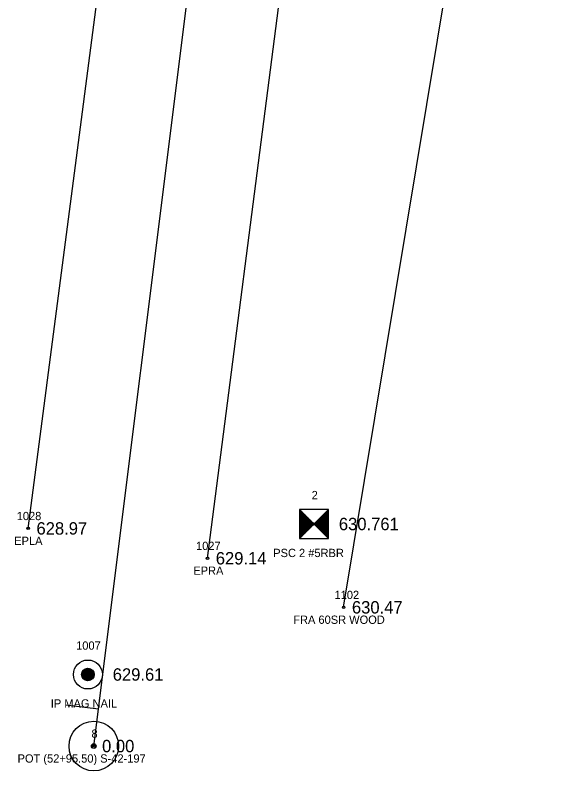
# Model space of a CAD drawing. Extents: x 1694813 to 1696862, y 1086485 to 1091027.
# Drawn here: x 1695856.6 to 1695921.9, y 1087535.6 to 1087627 of the extents above; entities that cross this region are included whole.
import ezdxf

# ---------------------------------------------------------------- set-up
doc = ezdxf.new("R2010")
doc.units = 0
for name, color, linetype in [('RD_EX_DV_Prop_txCode', 7, 'Continuous'), ('RD_EX_DV_PropPin', 7, 'Continuous'), ('RD_EX_Fence_Other', 7, 'Continuous'), ('RD_EX_Fence_Other_txCode', 7, 'Continuous'), ('RD_EX_Road', 7, 'Continuous'), ('RD_EX_Road_txCode', 7, 'Continuous'), ('RD_EX_TX_DV_Prop_ELEV', 7, 'Continuous'), ('RD_EX_TX_Fence_Other_ELEV', 7, 'Continuous'), ('RD_EX_TX_Road_ELEV', 7, 'Continuous'), ('RD_HC_Cl', 7, 'Continuous'), ('RD_HC_Data', 7, 'Continuous'), ('RD_HC_Data_Tic', 7, 'Continuous'), ('RD_HC_Survey', 7, 'Continuous'), ('RD_HC_Survey_ELEV', 7, 'Continuous'), ('RD_HC_txCode', 7, 'Continuous'), ('RD_SMD_Locator', 7, 'Continuous')]:
    doc.layers.add(name, color=color, linetype=linetype)

msp = doc.modelspace()

# ---------------------------------------------------------------- linework, layer by layer
at = {"layer": 'RD_EX_DV_PropPin'}
for p, q in [((1695864.674, 1087547.04), (1695864.674, 1087547.432)), ((1695864.709, 1087546.938), (1695864.709, 1087547.534)), ((1695864.744, 1087546.866), (1695864.744, 1087547.606)), ((1695864.779, 1087546.809), (1695864.779, 1087547.663)), ((1695864.814, 1087546.762), (1695864.814, 1087547.71)), ((1695864.849, 1087546.721), (1695864.849, 1087547.751)), ((1695864.884, 1087546.685), (1695864.884, 1087547.787)), ((1695864.919, 1087546.654), (1695864.919, 1087547.818)), ((1695864.954, 1087546.626), (1695864.954, 1087547.846)), ((1695864.989, 1087546.601), (1695864.989, 1087547.871)), ((1695865.024, 1087546.58), (1695865.024, 1087547.892)), ((1695865.059, 1087546.56), (1695865.059, 1087547.912)), ((1695865.094, 1087546.543), (1695865.094, 1087547.929)), ((1695865.129, 1087546.528), (1695865.129, 1087547.944)), ((1695865.164, 1087546.516), (1695865.164, 1087547.956)), ((1695865.199, 1087546.505), (1695865.199, 1087547.967)), ((1695865.234, 1087546.495), (1695865.234, 1087547.977)), ((1695865.269, 1087546.488), (1695865.269, 1087547.984)), ((1695865.304, 1087546.482), (1695865.304, 1087547.99)), ((1695865.339, 1087546.478), (1695865.339, 1087547.994)), ((1695865.374, 1087546.476), (1695865.374, 1087547.996)), ((1695865.409, 1087546.475), (1695865.409, 1087547.997)), ((1695865.444, 1087546.476), (1695865.444, 1087547.996)), ((1695865.479, 1087546.478), (1695865.479, 1087547.994)), ((1695865.514, 1087546.482), (1695865.514, 1087547.99)), ((1695865.549, 1087546.488), (1695865.549, 1087547.984)), ((1695865.584, 1087546.495), (1695865.584, 1087547.977)), ((1695865.619, 1087546.505), (1695865.619, 1087547.967)), ((1695865.654, 1087546.516), (1695865.654, 1087547.956)), ((1695865.689, 1087546.528), (1695865.689, 1087547.944)), ((1695865.724, 1087546.543), (1695865.724, 1087547.929)), ((1695865.759, 1087546.56), (1695865.759, 1087547.912)), ((1695865.794, 1087546.58), (1695865.794, 1087547.892)), ((1695865.829, 1087546.601), (1695865.829, 1087547.871)), ((1695865.864, 1087546.626), (1695865.864, 1087547.846)), ((1695865.899, 1087546.654), (1695865.899, 1087547.818)), ((1695865.934, 1087546.685), (1695865.934, 1087547.787)), ((1695865.969, 1087546.721), (1695865.969, 1087547.751)), ((1695866.004, 1087546.762), (1695866.004, 1087547.71)), ((1695866.039, 1087546.809), (1695866.039, 1087547.663)), ((1695866.074, 1087546.866), (1695866.074, 1087547.606)), ((1695866.109, 1087546.938), (1695866.109, 1087547.534)), ((1695866.144, 1087547.04), (1695866.144, 1087547.432))]:
    msp.add_line(p, q, dxfattribs=at)
for radius in [1.75, 0.761]:
    msp.add_circle((1695865.409, 1087547.236), radius, dxfattribs=at)
at = {"layer": 'RD_EX_Fence_Other'}
msp.add_lwpolyline([(1695896.342, 1087555.362), (1695913.969, 1087661.925), (1695929.73, 1087763.599), (1695939.841, 1087832.071), (1696009.841, 1087821.325)], dxfattribs=at)
at = {"layer": 'RD_EX_Road'}
for points in [[(1695879.875, 1087561.295), (1695893.332, 1087665.713), (1695905.959, 1087767.16), (1695918.657, 1087869.542), (1695930.865, 1087972.819), (1695936.258, 1088023.677), (1695942.136, 1088076.32), (1695948.067, 1088128.166), (1695955.04, 1088181.397), (1695962.876, 1088230.723), (1695971.68, 1088284.642), (1695982.023, 1088336.119), (1695993.277, 1088388.477), (1696018.751, 1088494.485), (1696045.231, 1088599.952), (1696055.716, 1088654.408), (1696060.146, 1088705.346), (1696055.832, 1088758.02), (1696044.006, 1088812.164), (1696026.404, 1088860.327), (1696000.406, 1088911.477), (1695972.46, 1088953.819), (1695939.476, 1088998.727), (1695931.206, 1088992.882)], [(1695858.187, 1087564.905), (1695871.711, 1087668.821), (1695884.505, 1087774.687), (1695887.48, 1087794.197), (1695897.565, 1087873.427), (1695908.916, 1087975.758), (1695914.491, 1088029.245), (1695917.654, 1088054.804), (1695920.274, 1088079.088), (1695926.979, 1088130.264), (1695934.746, 1088185.086), (1695942.155, 1088234.618), (1695951.36, 1088288.056), (1695961.479, 1088338.405), (1695972.862, 1088394.133), (1695998.526, 1088499.671), (1696024.807, 1088603.859), (1696034.83, 1088656.783)]]:
    msp.add_lwpolyline(points, dxfattribs=at)
at = {"layer": 'RD_HC_Cl'}
msp.add_line((1695866.122, 1087538.577), (1695910.685, 1087894.288), dxfattribs=at)
at = {"layer": 'RD_HC_Data'}
for radius in [3, 0.282]:
    msp.add_circle((1695866.122, 1087538.577), radius, dxfattribs=at)
at = {"layer": 'RD_HC_Data_Tic'}
msp.add_line((1695866.681, 1087543.042), (1695862.712, 1087543.539), dxfattribs=at)
at = {"layer": 'RD_HC_Survey'}
for p, q in [((1695891.011, 1087567.188), (1695894.511, 1087563.688)), ((1695894.511, 1087567.188), (1695891.011, 1087563.688)), ((1695891.035, 1087567.163), (1695891.035, 1087563.713)), ((1695891.06, 1087567.139), (1695891.06, 1087563.738)), ((1695891.085, 1087567.114), (1695891.085, 1087563.762)), ((1695891.11, 1087567.089), (1695891.11, 1087563.787)), ((1695891.134, 1087567.064), (1695891.134, 1087563.812)), ((1695891.159, 1087567.04), (1695891.159, 1087563.837)), ((1695891.184, 1087567.015), (1695891.184, 1087563.861)), ((1695891.209, 1087566.99), (1695891.209, 1087563.886)), ((1695891.233, 1087566.965), (1695891.233, 1087563.911)), ((1695891.258, 1087566.941), (1695891.258, 1087563.936)), ((1695891.283, 1087566.916), (1695891.283, 1087563.96)), ((1695891.308, 1087566.891), (1695891.308, 1087563.985)), ((1695891.332, 1087566.866), (1695891.332, 1087564.01)), ((1695891.357, 1087566.842), (1695891.357, 1087564.035)), ((1695891.382, 1087566.817), (1695891.382, 1087564.059)), ((1695891.407, 1087566.792), (1695891.407, 1087564.084)), ((1695891.431, 1087566.767), (1695891.431, 1087564.109)), ((1695891.456, 1087566.743), (1695891.456, 1087564.134)), ((1695891.481, 1087566.718), (1695891.481, 1087564.158)), ((1695891.506, 1087566.693), (1695891.506, 1087564.183)), ((1695891.53, 1087566.668), (1695891.53, 1087564.208)), ((1695891.555, 1087566.644), (1695891.555, 1087564.233)), ((1695891.58, 1087566.619), (1695891.58, 1087564.257)), ((1695891.605, 1087566.594), (1695891.605, 1087564.282)), ((1695891.629, 1087566.569), (1695891.629, 1087564.307)), ((1695891.654, 1087566.545), (1695891.654, 1087564.332)), ((1695891.679, 1087566.52), (1695891.679, 1087564.356)), ((1695891.704, 1087566.495), (1695891.704, 1087564.381)), ((1695891.728, 1087566.47), (1695891.728, 1087564.406)), ((1695891.753, 1087566.446), (1695891.753, 1087564.431)), ((1695891.778, 1087566.421), (1695891.778, 1087564.455)), ((1695891.803, 1087566.396), (1695891.803, 1087564.48)), ((1695893.719, 1087566.396), (1695893.719, 1087564.48)), ((1695893.743, 1087566.421), (1695893.743, 1087564.455)), ((1695893.768, 1087566.446), (1695893.768, 1087564.431)), ((1695893.793, 1087566.47), (1695893.793, 1087564.406)), ((1695893.818, 1087566.495), (1695893.818, 1087564.381)), ((1695893.842, 1087566.52), (1695893.842, 1087564.356)), ((1695893.867, 1087566.545), (1695893.867, 1087564.332)), ((1695893.892, 1087566.569), (1695893.892, 1087564.307)), ((1695893.917, 1087566.594), (1695893.917, 1087564.282)), ((1695893.941, 1087566.619), (1695893.941, 1087564.257)), ((1695893.966, 1087566.644), (1695893.966, 1087564.233)), ((1695893.991, 1087566.668), (1695893.991, 1087564.208)), ((1695894.016, 1087566.693), (1695894.016, 1087564.183)), ((1695894.04, 1087566.718), (1695894.04, 1087564.158)), ((1695894.065, 1087566.743), (1695894.065, 1087564.134)), ((1695894.09, 1087566.767), (1695894.09, 1087564.109)), ((1695894.115, 1087566.792), (1695894.115, 1087564.084)), ((1695894.139, 1087566.817), (1695894.139, 1087564.059)), ((1695894.164, 1087566.842), (1695894.164, 1087564.035)), ((1695894.189, 1087566.866), (1695894.189, 1087564.01)), ((1695894.214, 1087566.891), (1695894.214, 1087563.985)), ((1695894.238, 1087566.916), (1695894.238, 1087563.96)), ((1695894.263, 1087566.941), (1695894.263, 1087563.936)), ((1695894.288, 1087566.965), (1695894.288, 1087563.911)), ((1695894.313, 1087566.99), (1695894.313, 1087563.886)), ((1695894.337, 1087567.015), (1695894.337, 1087563.861)), ((1695894.362, 1087567.04), (1695894.362, 1087563.837)), ((1695894.387, 1087567.064), (1695894.387, 1087563.812)), ((1695894.412, 1087567.089), (1695894.412, 1087563.787)), ((1695894.436, 1087567.114), (1695894.436, 1087563.762)), ((1695894.461, 1087567.139), (1695894.461, 1087563.738)), ((1695894.486, 1087567.163), (1695894.486, 1087563.713)), ((1695891.827, 1087566.371), (1695891.827, 1087564.505)), ((1695891.852, 1087566.347), (1695891.852, 1087564.53)), ((1695891.877, 1087566.322), (1695891.877, 1087564.554)), ((1695891.902, 1087566.297), (1695891.902, 1087564.579)), ((1695891.926, 1087566.272), (1695891.926, 1087564.604)), ((1695891.951, 1087566.248), (1695891.951, 1087564.629)), ((1695891.976, 1087566.223), (1695891.976, 1087564.653)), ((1695892.001, 1087566.198), (1695892.001, 1087564.678)), ((1695892.025, 1087566.173), (1695892.025, 1087564.703)), ((1695892.05, 1087566.149), (1695892.05, 1087564.728)), ((1695892.075, 1087566.124), (1695892.075, 1087564.752)), ((1695892.1, 1087566.099), (1695892.1, 1087564.777)), ((1695892.124, 1087566.075), (1695892.124, 1087564.802)), ((1695892.149, 1087566.05), (1695892.149, 1087564.827)), ((1695892.174, 1087566.025), (1695892.174, 1087564.851)), ((1695892.199, 1087566), (1695892.199, 1087564.876)), ((1695892.223, 1087565.976), (1695892.223, 1087564.901)), ((1695892.248, 1087565.951), (1695892.248, 1087564.926)), ((1695892.273, 1087565.926), (1695892.273, 1087564.95)), ((1695892.298, 1087565.901), (1695892.298, 1087564.975)), ((1695892.322, 1087565.877), (1695892.322, 1087565)), ((1695892.347, 1087565.852), (1695892.347, 1087565.025)), ((1695892.372, 1087565.827), (1695892.372, 1087565.049)), ((1695892.397, 1087565.802), (1695892.397, 1087565.074)), ((1695892.421, 1087565.778), (1695892.421, 1087565.099)), ((1695892.446, 1087565.753), (1695892.446, 1087565.124)), ((1695892.471, 1087565.728), (1695892.471, 1087565.148)), ((1695892.496, 1087565.703), (1695892.496, 1087565.173)), ((1695892.52, 1087565.679), (1695892.52, 1087565.198)), ((1695892.545, 1087565.654), (1695892.545, 1087565.223)), ((1695892.57, 1087565.629), (1695892.57, 1087565.247)), ((1695892.595, 1087565.604), (1695892.595, 1087565.272)), ((1695892.619, 1087565.58), (1695892.619, 1087565.297)), ((1695892.644, 1087565.555), (1695892.644, 1087565.322)), ((1695892.669, 1087565.53), (1695892.669, 1087565.346)), ((1695892.694, 1087565.505), (1695892.694, 1087565.371)), ((1695892.718, 1087565.481), (1695892.718, 1087565.396)), ((1695892.803, 1087565.481), (1695892.803, 1087565.396)), ((1695892.828, 1087565.505), (1695892.828, 1087565.371)), ((1695892.852, 1087565.53), (1695892.852, 1087565.346)), ((1695892.877, 1087565.555), (1695892.877, 1087565.322)), ((1695892.902, 1087565.58), (1695892.902, 1087565.297)), ((1695892.927, 1087565.604), (1695892.927, 1087565.272)), ((1695892.951, 1087565.629), (1695892.951, 1087565.247)), ((1695892.976, 1087565.654), (1695892.976, 1087565.223)), ((1695893.001, 1087565.679), (1695893.001, 1087565.198)), ((1695893.026, 1087565.703), (1695893.026, 1087565.173)), ((1695893.05, 1087565.728), (1695893.05, 1087565.148)), ((1695893.075, 1087565.753), (1695893.075, 1087565.124)), ((1695893.1, 1087565.778), (1695893.1, 1087565.099)), ((1695893.125, 1087565.802), (1695893.125, 1087565.074)), ((1695893.149, 1087565.827), (1695893.149, 1087565.049)), ((1695893.174, 1087565.852), (1695893.174, 1087565.025)), ((1695893.199, 1087565.877), (1695893.199, 1087565)), ((1695893.224, 1087565.901), (1695893.224, 1087564.975)), ((1695893.248, 1087565.926), (1695893.248, 1087564.95)), ((1695893.273, 1087565.951), (1695893.273, 1087564.926)), ((1695893.298, 1087565.976), (1695893.298, 1087564.901)), ((1695893.323, 1087566), (1695893.323, 1087564.876)), ((1695893.347, 1087566.025), (1695893.347, 1087564.851)), ((1695893.372, 1087566.05), (1695893.372, 1087564.827)), ((1695893.397, 1087566.075), (1695893.397, 1087564.802)), ((1695893.422, 1087566.099), (1695893.422, 1087564.777)), ((1695893.446, 1087566.124), (1695893.446, 1087564.752)), ((1695893.471, 1087566.149), (1695893.471, 1087564.728)), ((1695893.496, 1087566.173), (1695893.496, 1087564.703)), ((1695893.521, 1087566.198), (1695893.521, 1087564.678)), ((1695893.545, 1087566.223), (1695893.545, 1087564.653)), ((1695893.57, 1087566.248), (1695893.57, 1087564.629)), ((1695893.595, 1087566.272), (1695893.595, 1087564.604)), ((1695893.62, 1087566.297), (1695893.62, 1087564.579)), ((1695893.644, 1087566.322), (1695893.644, 1087564.554)), ((1695893.669, 1087566.347), (1695893.669, 1087564.53)), ((1695893.694, 1087566.371), (1695893.694, 1087564.505)), ((1695892.743, 1087565.456), (1695892.743, 1087565.421)), ((1695892.778, 1087565.456), (1695892.778, 1087565.421))]:
    msp.add_line(p, q, dxfattribs=at)
msp.add_lwpolyline([(1695894.511, 1087567.188), (1695891.011, 1087567.188), (1695891.011, 1087563.688), (1695894.511, 1087563.688)], close=True, dxfattribs=at)
at = {"layer": 'RD_SMD_Locator'}
for centre in [(1695892.761, 1087565.438), (1695858.187, 1087564.905), (1695879.875, 1087561.295), (1695896.342, 1087555.362), (1695865.409, 1087547.236), (1695866.122, 1087538.577)]:
    msp.add_circle(centre, 0.15, dxfattribs=at)

# ---------------------------------------------------------------- texts
at = {"layer": 'RD_EX_DV_Prop_txCode'}
for s, p in [('1007', (1695863.984, 1087550.236)), ('IP MAG NAIL', (1695860.921, 1087543.236))]:
    msp.add_text(s, height=1, dxfattribs=at).set_placement(p)
at = {"layer": 'RD_EX_Fence_Other_txCode'}
for s, p in [('1102', (1695895.24, 1087556.362)), ('FRA 60SR WOOD', (1695890.248, 1087553.362))]:
    msp.add_text(s, height=1, dxfattribs=at).set_placement(p)
at = {"layer": 'RD_EX_Road_txCode'}
for s, p in [('1028', (1695856.801, 1087565.905)), ('EPLA', (1695856.494, 1087562.905)), ('1027', (1695878.489, 1087562.295)), ('EPRA', (1695878.158, 1087559.295))]:
    msp.add_text(s, height=1, dxfattribs=at).set_placement(p)
at = {"layer": 'RD_EX_TX_DV_Prop_ELEV'}
msp.add_text('629.61', height=1.5, dxfattribs=at).set_placement((1695868.409, 1087546.486))
at = {"layer": 'RD_EX_TX_Fence_Other_ELEV'}
msp.add_text('630.47', height=1.5, dxfattribs=at).set_placement((1695897.342, 1087554.612))
at = {"layer": 'RD_EX_TX_Road_ELEV'}
for s, p in [('628.97', (1695859.187, 1087564.155)), ('629.14', (1695880.875, 1087560.545))]:
    msp.add_text(s, height=1.5, dxfattribs=at).set_placement(p)
at = {"layer": 'RD_HC_Survey_ELEV'}
for s, p in [('630.761', (1695895.761, 1087564.688)), ('0.00', (1695867.122, 1087537.827))]:
    msp.add_text(s, height=1.5, dxfattribs=at).set_placement(p)
at = {"layer": 'RD_HC_txCode'}
for s, p in [('2', (1695892.477, 1087568.438)), ('PSC 2 #5RBR', (1695887.824, 1087561.438)), ('8', (1695865.838, 1087539.577)), ('POT (52+95.50) S-42-197', (1695856.901, 1087536.577))]:
    msp.add_text(s, height=1, dxfattribs=at).set_placement(p)

doc.saveas('drawing.dxf')
